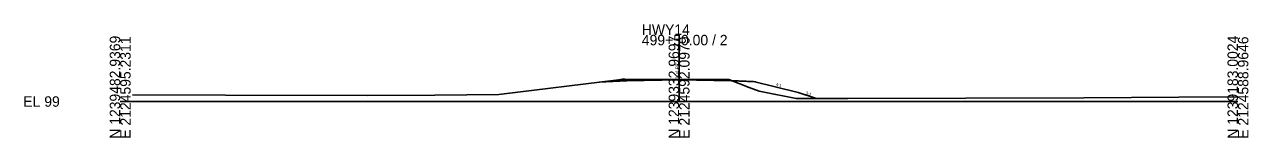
# Model space of a CAD drawing. Extents: x -26 to 303, y -10 to 11521.
# Drawn here: x -25.7 to 302.8, y 10990.3 to 11020.7 of the extents above; entities that cross this region are included whole.
import ezdxf

# ---------------------------------------------------------------- set-up
doc = ezdxf.new("R2010")
doc.units = 0
for name, color, linetype in [('XS_CELL', 7, 'Continuous'), ('XS_P_FINISHED_GRADE', 7, 'Continuous'), ('XS_P_SUBGRADE_GRANULAR', 7, 'Continuous'), ('XS_P_SUBGRADE_LEVELING', 7, 'Continuous'), ('XS_P_TX_FS_BS', 7, 'Continuous'), ('XS_X_GROUND', 7, 'Continuous'), ('XS_X_GROUND_TX', 7, 'Continuous')]:
    doc.layers.add(name, color=color, linetype=linetype)

msp = doc.modelspace()

# ---------------------------------------------------------------- linework, layer by layer
at = {"layer": 'XS_CELL'}
for p, q in [((150, 11000), (150, 11017.92)), ((0, 11000), (150, 11000)), ((150, 11000), (300, 11000))]:
    msp.add_line(p, q, dxfattribs=at)
at = {"layer": 'XS_P_FINISHED_GRADE'}
for p, q in [((150, 11005.92), (136, 11005.64)), ((150, 11005.92), (164, 11005.64)), ((136, 11005.64), (130.08, 11005.41)), ((164, 11005.64), (170, 11005.4)), ((170, 11005.4), (182, 11002.4)), ((182, 11002.4), (186.86, 11000.78))]:
    msp.add_line(p, q, dxfattribs=at)
at = {"layer": 'XS_P_SUBGRADE_GRANULAR'}
for p, q in [((136, 11005.52), (128.58, 11005.22)), ((128.58, 11005.22), (130.08, 11005.41)), ((164, 11005.52), (170.6, 11005.25))]:
    msp.add_line(p, q, dxfattribs=at)
at = {"layer": 'XS_P_SUBGRADE_LEVELING'}
for p, q in [((150, 11005.8), (136, 11005.52)), ((136, 11005.52), (136, 11005.64)), ((150, 11005.8), (164, 11005.52)), ((164, 11005.52), (164, 11005.64))]:
    msp.add_line(p, q, dxfattribs=at)
at = {"layer": 'XS_X_GROUND'}
for p, q in [((101.63, 11001.9), (133.72, 11005.86)), ((133.72, 11005.86), (134.7, 11005.97)), ((134.7, 11005.97), (135.43, 11005.97)), ((135.43, 11005.97), (150, 11005.92)), ((150, 11005.92), (163.33, 11005.88)), ((163.33, 11005.88), (168.78, 11003.8)), ((168.78, 11003.8), (171.53, 11002.75)), ((171.53, 11002.75), (172.37, 11002.58)), ((172.37, 11002.58), (181.43, 11000.77)), ((3.33, 11001.82), (28.28, 11001.74)), ((28.28, 11001.74), (66.44, 11001.58)), ((66.44, 11001.58), (84.47, 11001.72)), ((84.47, 11001.72), (101.63, 11001.9)), ((181.43, 11000.77), (192.19, 11000.8)), ((192.19, 11000.8), (192.66, 11000.8)), ((192.66, 11000.8), (195.29, 11000.81)), ((195.29, 11000.81), (258.66, 11000.97)), ((258.66, 11000.97), (284.12, 11001.19)), ((284.12, 11001.19), (300, 11001.26))]:
    msp.add_line(p, q, dxfattribs=at)

# ---------------------------------------------------------------- texts
at = {"layer": 'XS_CELL'}
for s, p in [('HWY14', (140, 11017.92)), ('499+50.00 / 2', (140, 11015.12)), ('EL 99', (-26, 10998.6))]:
    msp.add_text(s, height=2.8, dxfattribs=at).set_placement(p)
for s, p in [('N 1239482.9369', (0, 10990)), ('E 2124595.2311', (2.8, 10990)), ('N 1239332.9697', (150, 10990)), ('E 2124592.0979', (152.8, 10990)), ('N 1239183.0024', (300, 10990)), ('E 2124588.9646', (302.8, 10990))]:
    msp.add_text(s, height=2.8, rotation=90, dxfattribs=at).set_placement(p)
at = {"layer": 'XS_P_TX_FS_BS'}
for s, rotation, p in [('4:1', 345.9638, (175.94, 11004.27)), ('3:1', 341.5651, (183.89, 11001.97))]:
    msp.add_text(s, height=0.8, rotation=rotation, dxfattribs=at).set_placement(p)
at = {"layer": 'XS_X_GROUND_TX'}
msp.add_text('104.92', height=1, rotation=90, dxfattribs=at).set_placement((150, 11006.02))

doc.saveas('drawing.dxf')
